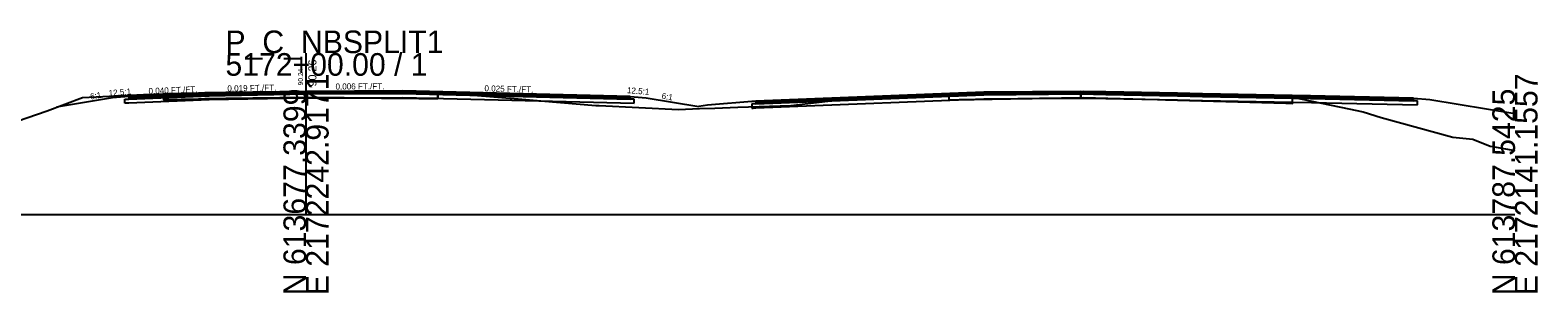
# Model space of a CAD drawing. Extents: x -26 to 1303, y -3010 to 12038.
# Drawn here: x 115.8 to 302.8, y 490.3 to 522.8 of the extents above; entities that cross this region are included whole.
import ezdxf

# ---------------------------------------------------------------- set-up
doc = ezdxf.new("R2010")
doc.units = 0
for name, color, linetype in [('RD_GPK_XS_Cell', 7, 'Continuous'), ('RD_XS_Base', 7, 'Continuous'), ('RD_XS_ExGround', 7, 'Continuous'), ('RD_XS_ExPaveRet', 7, 'Continuous'), ('RD_XS_Greenside', 7, 'Continuous'), ('RD_XS_Pave', 7, 'Continuous'), ('RD_XS_PaveOvlay_CP', 7, 'Continuous'), ('RD_XS_TieSlope', 7, 'Continuous'), ('RD_XS_TX_Elev_EX', 7, 'Continuous'), ('RD_XS_TX_Elev_PR', 7, 'Continuous'), ('RD_XS_TX_ShdSlope', 7, 'Continuous'), ('RD_XS_TX_Slope', 7, 'Continuous')]:
    doc.layers.add(name, color=color, linetype=linetype)

msp = doc.modelspace()

# ---------------------------------------------------------------- linework, layer by layer
at = {"layer": 'RD_GPK_XS_Cell'}
for p, q in [((150, 500), (150, 520)), ((0, 500), (150, 500)), ((150, 500), (300, 500))]:
    msp.add_line(p, q, dxfattribs=at)
at = {"layer": 'RD_XS_Base'}
for p, q in [((128, 514.31), (138, 514.71)), ((138, 514.71), (150, 514.94)), ((138, 514.71), (138, 514.71)), ((150, 514.94), (150, 515.1)), ((150, 515.1), (150, 514.44)), ((162, 515.01), (150, 514.94)), ((150, 514.94), (150, 514.94)), ((150, 514.94), (150, 514.44)), ((150, 514.44), (162, 514.51)), ((190.21, 514.31), (162, 515.01)), ((162.01, 514.51), (190.7, 513.8)), ((164, 514.93), (164, 514.93)), ((164, 514.93), (164, 514.93)), ((226.73, 514.55), (205.83, 513.72)), ((234.12, 514.85), (226.73, 514.55)), ((246.12, 514.94), (234.12, 514.85)), ((234.12, 514.35), (246.12, 514.44)), ((246.12, 515.06), (246.12, 515.1)), ((246.12, 515.1), (246.12, 514.93)), ((246.12, 514.94), (246.12, 515.06)), ((249.25, 514.88), (246.12, 514.94)), ((246.12, 514.81), (246.12, 514.94)), ((246.12, 514.93), (246.12, 514.44)), ((246.12, 514.44), (246.12, 514.81)), ((246.12, 514.44), (249.25, 514.38)), ((258.12, 514.7), (249.25, 514.88)), ((261.25, 514.64), (258.12, 514.7)), ((270.12, 514.46), (261.25, 514.64)), ((274.64, 514.37), (270.12, 514.46)), ((127.5, 514.29), (128, 514.31)), ((127.5, 513.79), (127.5, 514.29)), ((127.5, 514.29), (127.5, 514.29)), ((128, 513.81), (127.5, 513.79)), ((127.5, 513.79), (127.5, 513.79)), ((127.5, 513.79), (127.5, 513.79)), ((128, 514.31), (128, 514.31)), ((138, 514.21), (128, 513.81)), ((128, 513.81), (128, 513.81)), ((150, 514.44), (138, 514.21)), ((138, 514.21), (138, 514.21)), ((150, 514.44), (150, 514.44)), ((150, 514.44), (150, 514.44)), ((164, 514.43), (164, 514.43)), ((164, 514.43), (164, 514.43)), ((190.2, 514.31), (190.2, 514.31)), ((190.7, 514.3), (190.21, 514.31)), ((190.7, 513.8), (190.7, 514.3)), ((190.7, 514.29), (190.7, 514.29)), ((205.46, 513.7), (205.33, 513.7)), ((205.33, 513.7), (205.33, 513.33)), ((205.33, 513.33), (205.33, 513.2)), ((205.33, 513.2), (205.46, 513.2)), ((205.83, 513.72), (205.46, 513.7)), ((205.46, 513.2), (205.83, 513.22)), ((205.83, 513.22), (226.73, 514.05)), ((226.73, 514.05), (234.12, 514.35)), ((249.25, 514.38), (258.12, 514.2)), ((258.12, 514.2), (261.25, 514.14)), ((261.25, 514.14), (270.12, 513.96)), ((270.12, 513.96), (274.77, 513.87)), ((287.42, 514.11), (274.64, 514.37)), ((274.77, 513.87), (287.92, 513.6)), ((287.55, 514.11), (287.42, 514.11)), ((287.92, 514.1), (287.55, 514.11)), ((287.92, 513.97), (287.92, 514.1)), ((287.92, 513.6), (287.92, 513.97))]:
    msp.add_line(p, q, dxfattribs=at)
at = {"layer": 'RD_XS_ExGround'}
msp.add_lwpolyline([(112.97, 511.15), (117.88, 512.87), (122.28, 514.51), (129.82, 514.88), (132.36, 514.96), (136.64, 515.05), (137.46, 515.07), (140.07, 515.12), (150.12, 515.24), (163.98, 515.15), (166.36, 515.15), (167.75, 515.02), (176.34, 514.34), (179.15, 514.11), (185.96, 513.53), (186.13, 513.52), (186.31, 513.5), (186.37, 513.5), (196.2, 513.03), (198.83, 513.13), (200.71, 513.2), (203.58, 513.29), (210.16, 513.53), (212.25, 513.74), (218.62, 514.49), (219.28, 514.5), (228.57, 514.9), (228.94, 514.92), (229.76, 514.97), (230.93, 514.99), (232.39, 515.01), (237.41, 515.1), (246.43, 515.24), (256.65, 514.96), (272.4, 514.53), (279.39, 513.12), (281.16, 512.74), (283.41, 512.03), (292.31, 509.57), (293.13, 509.51), (294.77, 509.34), (296.93, 508.46), (297.2, 508.42), (300, 507.94)], dxfattribs=at)
at = {"layer": 'RD_XS_ExPaveRet'}
for p, q in [((163.98, 515.15), (150.12, 515.24)), ((166.36, 515.15), (163.98, 515.15)), ((256.65, 514.96), (255.63, 514.99)), ((272.4, 514.53), (272.4, 514.53))]:
    msp.add_line(p, q, dxfattribs=at)
for points in [[(166.36, 515.15), (166.36, 515.15), (166.36, 514.4), (166.36, 514.4), (166.36, 514.4), (163.98, 514.4), (163.98, 514.4), (150.12, 514.49), (150.12, 514.49), (150.12, 514.49), (140.07, 514.37), (137.46, 514.32), (137.46, 514.32), (136.64, 514.3), (132.36, 514.21), (132.36, 514.21), (132.36, 514.21), (132.36, 514.21), (132.36, 514.96), (132.36, 514.96), (132.36, 514.96), (136.64, 515.05), (137.46, 515.07), (137.46, 515.07), (140.07, 515.12), (150.12, 515.24), (150.12, 515.24), (150.12, 515.24), (163.98, 515.15), (163.98, 515.15), (166.36, 515.15)], [(150.12, 515.24), (140.07, 515.12), (137.46, 515.07), (136.64, 515.05), (132.36, 514.96)], [(132.36, 514.96), (132.36, 514.21), (136.64, 514.3), (137.46, 514.32), (140.07, 514.37), (150.12, 514.49), (163.98, 514.4), (166.36, 514.4), (166.36, 515.15)], [(272.4, 514.53), (271.56, 514.55), (256.65, 514.96), (255.63, 514.99), (246.43, 515.24), (238.3, 515.11), (237.41, 515.1), (232.89, 515.02), (231.31, 514.99), (231.02, 514.99), (229.76, 514.97), (229.76, 514.27), (229.76, 514.22), (231.02, 514.24), (231.31, 514.24), (232.89, 514.27), (237.41, 514.35), (238.3, 514.36), (246.43, 514.49), (255.63, 514.24), (256.65, 514.21), (271.56, 513.8), (272.4, 513.78), (272.4, 513.78), (272.4, 513.78), (272.4, 513.83), (272.4, 514.53), (272.4, 514.53), (272.4, 514.53)], [(238.3, 515.11), (237.41, 515.1), (232.89, 515.02), (232.39, 515.01), (230.93, 514.99), (229.76, 514.97)], [(229.76, 514.97), (229.76, 514.27), (229.76, 514.22), (231.02, 514.24), (231.31, 514.24), (232.89, 514.27), (237.41, 514.35), (238.3, 514.36), (246.43, 514.49), (255.63, 514.24), (256.65, 514.21), (271.56, 513.8), (272.4, 513.78), (272.4, 513.78), (272.4, 513.83), (272.4, 514.53)], [(255.63, 514.99), (246.43, 515.24), (238.3, 515.11)], [(272.4, 514.53), (271.56, 514.55), (256.65, 514.96)]]:
    msp.add_lwpolyline(points, dxfattribs=at)
at = {"layer": 'RD_XS_Greenside'}
for p, q in [((126, 514.47), (119.06, 513.31)), ((192.2, 514.47), (198.75, 513.37)), ((199.83, 513.55), (198.75, 513.37)), ((289.42, 514.27), (300, 512.51))]:
    msp.add_line(p, q, dxfattribs=at)
at = {"layer": 'RD_XS_Pave'}
for p, q in [((138, 515.03), (128, 514.63)), ((138, 514.87), (128, 514.47)), ((128, 514.47), (138, 514.87)), ((128, 514.31), (138, 514.71)), ((128, 514.63), (128, 514.63)), ((128, 514.63), (128, 514.47)), ((128, 514.47), (128, 514.47)), ((128, 514.47), (128, 514.31)), ((128, 514.47), (128, 514.47)), ((128, 514.47), (128, 514.47)), ((150, 515.26), (138, 515.03)), ((150, 515.1), (138, 514.87)), ((138, 514.87), (150, 515.1)), ((138, 515.03), (138, 515.03)), ((138, 514.71), (150, 514.94)), ((138, 514.87), (138, 514.87)), ((138, 514.87), (138, 514.87)), ((138, 514.71), (138, 514.71)), ((162, 515.33), (150, 515.26)), ((162, 515.17), (150, 515.1)), ((150, 515.1), (162, 515.17)), ((150, 515.1), (150, 514.94)), ((150, 514.94), (150, 515.1)), ((150, 514.94), (162, 515.01)), ((150, 514.94), (150, 514.94)), ((150, 514.94), (150, 514.94)), ((190.2, 514.63), (162, 515.33)), ((190.21, 514.47), (162, 515.17)), ((162, 515.17), (190.21, 514.47)), ((162, 515.01), (190.21, 514.31)), ((164, 515.25), (164, 515.25)), ((164, 515.25), (164, 515.25)), ((164, 515.09), (164, 515.09)), ((164, 515.09), (164, 515.09)), ((164, 515.09), (164, 515.09)), ((164, 515.09), (164, 515.09)), ((164, 514.93), (164, 514.93)), ((164, 514.93), (164, 514.93)), ((190.2, 514.47), (190.2, 514.63)), ((190.2, 514.63), (190.2, 514.63)), ((190.2, 514.31), (190.2, 514.47)), ((190.2, 514.47), (190.2, 514.47)), ((226.73, 514.87), (205.83, 514.03)), ((226.73, 514.71), (205.83, 513.88)), ((205.83, 513.88), (226.73, 514.71)), ((205.83, 513.72), (226.73, 514.55)), ((234.12, 515.17), (226.73, 514.87)), ((234.12, 515.01), (226.73, 514.71)), ((226.73, 514.71), (234.12, 515.01)), ((226.73, 514.55), (234.12, 514.85)), ((246.12, 515.26), (234.12, 515.17)), ((246.12, 515.1), (234.12, 515.01)), ((234.12, 515.01), (246.12, 515.1)), ((234.12, 514.85), (246.12, 514.94)), ((249.25, 515.2), (246.12, 515.26)), ((246.12, 515.06), (246.12, 515.1)), ((246.12, 515.1), (249.25, 515.04)), ((249.25, 515.04), (246.12, 515.1)), ((246.12, 515.1), (246.12, 515.06)), ((246.12, 514.94), (246.12, 515.06)), ((246.12, 515.06), (246.12, 514.94)), ((246.12, 514.94), (249.25, 514.88)), ((258.12, 515.02), (249.25, 515.2)), ((249.25, 515.04), (258.12, 514.86)), ((258.12, 514.86), (249.25, 515.04)), ((249.25, 514.88), (258.12, 514.7)), ((261.25, 514.96), (258.12, 515.02)), ((258.12, 514.86), (261.25, 514.8)), ((261.25, 514.8), (258.12, 514.86)), ((258.12, 514.7), (261.25, 514.64)), ((270.12, 514.78), (261.25, 514.96)), ((261.25, 514.8), (270.12, 514.62)), ((270.12, 514.62), (261.25, 514.8)), ((261.25, 514.64), (270.12, 514.46)), ((274.64, 514.69), (270.12, 514.78)), ((270.12, 514.62), (274.64, 514.53)), ((274.64, 514.53), (270.12, 514.62)), ((270.12, 514.46), (274.64, 514.37)), ((287.42, 514.43), (274.64, 514.69)), ((274.64, 514.53), (287.42, 514.27)), ((287.42, 514.27), (274.64, 514.53)), ((128, 514.31), (128, 514.31)), ((128, 514.31), (128, 514.31)), ((205.83, 514.03), (205.83, 513.92)), ((205.83, 513.92), (205.83, 513.88)), ((205.83, 513.88), (205.83, 513.76)), ((205.83, 513.76), (205.83, 513.72)), ((274.64, 514.37), (287.42, 514.11)), ((287.42, 514.39), (287.42, 514.43)), ((287.42, 514.27), (287.42, 514.39)), ((287.42, 514.23), (287.42, 514.27)), ((287.42, 514.11), (287.42, 514.23))]:
    msp.add_line(p, q, dxfattribs=at)
at = {"layer": 'RD_XS_PaveOvlay_CP'}
for p, q in [((138, 515.03), (128, 514.63)), ((128, 514.63), (128, 514.63)), ((150, 515.26), (138, 515.03)), ((138, 515.03), (138, 515.03)), ((162, 515.33), (150, 515.26)), ((190.2, 514.63), (162, 515.33)), ((164, 515.25), (164, 515.25)), ((164, 515.25), (164, 515.25)), ((226.73, 514.87), (205.83, 514.03)), ((234.12, 515.17), (226.73, 514.87)), ((246.12, 515.26), (234.12, 515.17)), ((249.25, 515.2), (246.12, 515.26)), ((258.12, 515.02), (249.25, 515.2)), ((261.25, 514.96), (258.12, 515.02)), ((270.12, 514.78), (261.25, 514.96)), ((274.64, 514.69), (270.12, 514.78)), ((287.42, 514.43), (274.64, 514.69))]:
    msp.add_line(p, q, dxfattribs=at)
at = {"layer": 'RD_XS_TieSlope'}
for p, q in [((128, 514.63), (126, 514.47)), ((190.2, 514.63), (192.2, 514.47)), ((205.83, 514.03), (199.83, 513.55)), ((287.42, 514.43), (289.42, 514.27))]:
    msp.add_line(p, q, dxfattribs=at)

# ---------------------------------------------------------------- texts
at = {"layer": 'RD_GPK_XS_Cell'}
for s, p in [('P_C_NBSPLIT1', (140, 520)), ('5172+00.00 / 1', (140, 517.2))]:
    msp.add_text(s, height=2.8, dxfattribs=at).set_placement(p)
for s, p in [('E 2172242.9171', (152.8, 490)), ('E 2172141.1557', (302.8, 490)), ('N 613677.3399', (150, 490)), ('N 613787.5425', (300, 490))]:
    msp.add_text(s, height=2.8, rotation=90, dxfattribs=at).set_placement(p)
at = {"layer": 'RD_XS_TX_Elev_EX'}
msp.add_text('90.24', height=0.6, rotation=90, dxfattribs=at).set_placement((149.62, 516))
at = {"layer": 'RD_XS_TX_Elev_PR'}
msp.add_text('90.26', height=1, rotation=90, dxfattribs=at).set_placement((151.29, 515.86))
at = {"layer": 'RD_XS_TX_ShdSlope'}
for rotation, p in [(4.5739, (125.54, 514.67)), (355.4261, (189.79, 515.05))]:
    msp.add_text('12.5:1', height=0.75, rotation=rotation, dxfattribs=at).set_placement(p)
at = {"layer": 'RD_XS_TX_Slope'}
for s, rotation, p in [('0.006 FT./FT.', 0.3586, (153.66, 515.49)), ('6:1', 9.4623, (123.28, 514.24)), ('0.040 FT./FT.', 2.2906, (130.47, 514.92)), ('0.019 FT./FT.', 1.0975, (140.25, 515.25)), ('0.025 FT./FT.', 358.5679, (172.13, 515.27)), ('6:1', 350.5358, (194.08, 514.36))]:
    msp.add_text(s, height=0.75, rotation=rotation, dxfattribs=at).set_placement(p)

doc.saveas('drawing.dxf')
